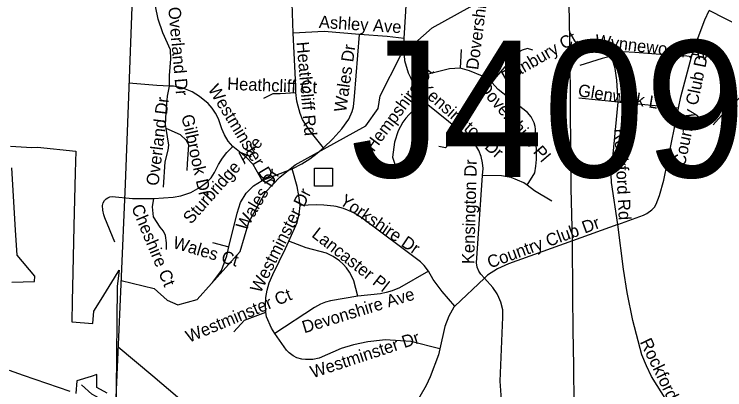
# Model space of a CAD drawing. Extents: x 1662474 to 1856135, y 779280 to 917889.
# Drawn here: x 1689866 to 1695335, y 806742 to 809631 of the extents above; entities that cross this region are included whole.
import ezdxf

# ---------------------------------------------------------------- set-up
doc = ezdxf.new("R2010")
doc.units = 0
for name, color, linetype in [('Exist Boundary Political City Limit New', 7, 'Continuous'), ('Exist Boundary Political CountyLine', 7, 'Continuous'), ('Exist Hydrographic Misc Water Feature', 7, 'Continuous'), ('Exist Road Non-System Structure Non-Sys Other Attributed CELL', 7, 'Continuous'), ('Exist Road Non-System Structure Non-Sys Other Number Label', 7, 'Continuous'), ('Exist Road Non-System Type 51', 7, 'Continuous'), ('Exist Road Non-System Type 51 Label', 7, 'Continuous'), ('Exist Road Primary NC UnDivided 4 Lane Attributed', 7, 'Continuous'), ('Exist Utilities Electrical Transmission Line', 7, 'Continuous'), ('Map Preparation Boundary City Limit Buffer Line', 7, 'Continuous')]:
    doc.layers.add(name, color=color, linetype=linetype)

msp = doc.modelspace()

# ---------------------------------------------------------------- linework, layer by layer
at = {"layer": 'Exist Boundary Political City Limit New'}
for points in [[(1689837.1, 808615.6), (1690000, 808604.7), (1690043.8, 808608.4), (1690340.6, 808577.1), (1690335.5, 808412.5), (1690325.8, 807999.6), (1690317.2, 807643.2), (1690312, 807424.1), (1690308.1, 807264.9), (1690471.4, 807251.4), (1690478.6, 807345.9), (1690534.4, 807436.7), (1690637, 807603.6), (1690672.9, 807662.2), (1690658.5, 807536.2), (1690650.1, 806742.6), (1690649.5, 806684.6)], [(1689847.1, 807570.9), (1690022, 807574.9), (1690023.4, 807615.5), (1689888.4, 807778.2), (1689876.1, 807969.6), (1689847.1, 808450.2)], [(1690297.2, 806728.5), (1689937.1, 806852.2), (1689828.1, 806890)], [(1690581.5, 806715.2), (1690502.5, 806759.9), (1690500.4, 806859.4), (1690457.6, 806845.6), (1690346.6, 806809.9), (1690339, 806714.1)]]:
    msp.add_lwpolyline(points, dxfattribs=at)
at = {"layer": 'Exist Boundary Political CountyLine'}
msp.add_lwpolyline([(1690220.4, 796849.4), (1690253.3, 797643.4), (1690261, 798032.2), (1690301.7, 799178.2), (1690347.6, 800042.9), (1690382.7, 800862.5), (1690417.8, 801672.6), (1690459.9, 802612.4), (1690490.6, 803379.9), (1690531.6, 804201.7), (1690578.3, 805157.6), (1690614.8, 805955.1), (1690649.3, 806683.1), (1690688.7, 807554.8), (1690723, 808322.5), (1690748.6, 808998.5), (1690777.2, 809760.4), (1690803.1, 810502.1), (1690838, 811298), (1690892.7, 812263.6), (1690949.1, 813375.2), (1690989.8, 814167.1), (1691300.1, 821093.4)], dxfattribs=at)
at = {"layer": 'Exist Hydrographic Misc Water Feature'}
msp.add_lwpolyline([(1690689.9, 807582.2), (1690942.8, 807521.7), (1691041.8, 807431.1), (1691124.8, 807396.6), (1691274.8, 807436.2), (1691603.8, 807807), (1691672.8, 808032), (1691800.9, 808262.6), (1691910.9, 808378.5), (1692027.9, 808471.3), (1692572.9, 808772), (1692665.9, 808904.7), (1692683.8, 809002.8), (1692837.8, 809311.5), (1693081.8, 809526.5), (1693374.9, 809688), (1693492.9, 809787.3)], dxfattribs=at)
at = {"layer": 'Exist Road Non-System Structure Non-Sys Other Attributed CELL'}
msp.add_lwpolyline([(1692177.5, 808447.2), (1692316.4, 808447.2), (1692316.4, 808308.1), (1692177.5, 808308.1)], close=True, dxfattribs=at)
at = {"layer": 'Exist Road Non-System Type 51'}
for p, q in [((1695584.6, 809469.9), (1695215.2, 809660.4)), ((1693305.4, 809359.4), (1693297.5, 809216.1)), ((1694513.8, 808954.4), (1694210.9, 808984.2)), ((1694978.2, 808908.2), (1694513.8, 808954.4)), ((1691773.1, 808351.8), (1692005.4, 808441.8)), ((1694511.1, 808012.9), (1694162.6, 807887.8)), ((1691391.1, 807874.4), (1691518, 807841.2)), ((1693485.1, 807600.4), (1693257.1, 807386.4))]:
    msp.add_line(p, q, dxfattribs=at)
for points in [[(1692014, 809484.9), (1692005.1, 809715.8), (1692005.4, 810474.9), (1692024, 810718.1), (1692023.2, 810769.6), (1692013.5, 810852.5), (1691986.8, 810965.9)], [(1691060, 809078), (1691061, 809160.4), (1691071.5, 809287.9), (1691067.4, 809357.5), (1691009.9, 809487.2), (1690972.6, 809593.8), (1690952.9, 809693.5), (1690940.6, 809800.6)], [(1692866.5, 809444.4), (1692885.6, 809740.2), (1692891.6, 809785.9)], [(1695079.1, 809303.7), (1695108.1, 809390.1), (1695182.2, 809587.2), (1695215.2, 809660.4)], [(1692522.6, 809474.9), (1692250.2, 809498.8), (1692014, 809484.9)], [(1692032.4, 809027.9), (1692034.2, 809076.7), (1692014, 809484.9)], [(1692245.8, 808604), (1692318, 808672.5), (1692387, 808749.9), (1692442.4, 808824.8), (1692467.9, 808881.4), (1692476, 808917.4), (1692485.1, 808998.8), (1692522.6, 809474.9)], [(1692866.5, 809444.4), (1692735.2, 809458.9), (1692522.6, 809474.9)], [(1695584.6, 809469.9), (1695551, 809398.4), (1695514.8, 809287.4), (1695497.1, 809195.9), (1695489, 809099.5), (1695482.5, 809057.8), (1695473.6, 809032.9), (1695449.1, 808987.2), (1695407.9, 808947.2), (1695330.8, 808873.9), (1695245.5, 808779.4)], [(1692921.6, 809135.8), (1692900.4, 809177.5), (1692873.4, 809271.7), (1692866.5, 809362.8), (1692866.5, 809444.4)], [(1693857.6, 809354.9), (1693816.1, 809365.9), (1693775.9, 809353.4), (1693729.8, 809329.4), (1693689.6, 809287.4), (1693641.6, 809226.9), (1693574.6, 809150.2), (1693541, 809105.6)], [(1695079.1, 809303.7), (1695042.1, 809309.2), (1694874.1, 809318.7), (1694641.9, 809336.5), (1694553.1, 809340.4), (1694464.4, 809307.7)], [(1694464.4, 809307.7), (1694390.1, 809291.1), (1694218.8, 809236.2)], [(1694513.8, 808954.4), (1694503.2, 809124.7), (1694490.4, 809213.4), (1694464.4, 809307.7)], [(1694978.2, 808908.2), (1694995.9, 808994.2), (1695079.1, 809303.7)], [(1693297.5, 809216.1), (1693217.1, 809209.5), (1692921.6, 809135.8)], [(1693541, 809105.6), (1693469.9, 809155.2), (1693371, 809196.6), (1693297.5, 809216.1)], [(1693028.4, 808955.4), (1692992.8, 808997.7), (1692958.1, 809052.2), (1692921.6, 809135.8)], [(1691060, 809078), (1690962.6, 809083.2), (1690747.1, 809099.5)], [(1691035.4, 808752.2), (1691029.9, 808782.8), (1691034.2, 808878.2), (1691045.2, 809000.4), (1691060, 809078)], [(1691547.6, 808614.2), (1691512.8, 808654.4), (1691483.1, 808703.2), (1691462.9, 808748.4), (1691436.9, 808827.4), (1691415.9, 808869.4), (1691389.4, 808908.2), (1691357.6, 808943.1), (1691291.2, 808998.5), (1691235.6, 809032.9), (1691157.4, 809064.4), (1691092.5, 809077.5), (1691060, 809078)], [(1693812.9, 808314.8), (1693873.6, 808410), (1693881.4, 808462), (1693885.9, 808514.2), (1693885.9, 808580.1), (1693878.6, 808745.8), (1693875.4, 808767.5), (1693867.5, 808795.9), (1693844.1, 808841.5), (1693816.1, 808875.4), (1693591.9, 809052.8), (1693541, 809105.6)], [(1691786.5, 808986.4), (1691860, 809021.6), (1691913.2, 809021.6), (1692032.4, 809027.9)], [(1692245.8, 808604), (1692144.5, 808732.6), (1692102.5, 808792.7), (1692085.9, 808821.6), (1692066.8, 808866.7), (1692050.2, 808923.9), (1692041.9, 808962), (1692032.4, 809027.9)], [(1693028.4, 808955.4), (1692959.9, 808910), (1692904.9, 808860.4), (1692879.6, 808831.5), (1692857.9, 808800.4), (1692822.1, 808734.4), (1692793.9, 808646.8), (1692777, 808530.8), (1692803.2, 808454.9)], [(1693301.1, 808731.2), (1693036.6, 808944.9), (1693028.4, 808955.4)], [(1694511.1, 808012.9), (1694462.5, 808337.4), (1694460.6, 808395.6), (1694513.8, 808954.4)], [(1694511.1, 808012.9), (1694710.1, 808085.9), (1694735.2, 808097.9), (1694774.4, 808127.4), (1694793.2, 808147.9), (1694807.9, 808169.6), (1694831.9, 808236.9), (1694865.4, 808355.4), (1694978.2, 808908.2)], [(1691013.8, 808299.5), (1691026.6, 808494.9), (1691050.9, 808584.4), (1691055.5, 808624.4), (1691035.4, 808752.2)], [(1691198, 808427.6), (1691199.4, 808480.4), (1691210.6, 808625.8), (1691189.9, 808662.8), (1691146.6, 808702.7), (1691035.4, 808752.2)], [(1693301.1, 808731.2), (1693185.9, 808601.9), (1693135, 808612.7)], [(1693470.6, 808389.9), (1693474.1, 808444.4), (1693470.4, 808488.5), (1693459.4, 808536.8), (1693441, 808582.5), (1693418.8, 808620.5), (1693387.8, 808659.1), (1693359.4, 808685.4), (1693301.1, 808731.2)], [(1690939.8, 808214), (1691089.9, 808223.7), (1691148.1, 808232.9), (1691225.1, 808260.7), (1691296.5, 808300.4), (1691348.1, 808338.7), (1691381.5, 808372.8), (1691408.2, 808412.7), (1691439, 808475.9), (1691468.1, 808523.4), (1691502.2, 808567.8), (1691547.6, 808614.2)], [(1691773.1, 808351.8), (1691704.1, 808474.4), (1691651.9, 808532.4), (1691547.6, 808614.2)], [(1692005.4, 808441.8), (1692079.9, 808480.6), (1692140.5, 808518.4), (1692197.5, 808561.8), (1692245.8, 808604)], [(1692067.6, 808160.7), (1692057.1, 808233.4), (1692042.9, 808305.6), (1692005.4, 808441.8)], [(1691518, 807841.2), (1691582.6, 808100.4), (1691607.5, 808181.9), (1691650.2, 808253.6), (1691706.6, 808311.6), (1691773.1, 808351.8)], [(1693485.1, 807600.4), (1693457.4, 807631.6), (1693442.6, 807654.9), (1693430, 807685.9), (1693424.2, 807718.7), (1693470.6, 808389.9)], [(1693812.9, 808314.8), (1693789.4, 808332.9), (1693690.6, 808374.1), (1693616.4, 808388.8), (1693470.6, 808389.9)], [(1694005.1, 808192.4), (1693871.5, 808271.2), (1693812.9, 808314.8)], [(1690639.8, 807878.5), (1690563.4, 808064.9), (1690556.4, 808086.7), (1690548.6, 808123.2), (1690545, 808160.4), (1690549.5, 808179.9), (1690561, 808198.8), (1690572.9, 808210.6), (1690586.8, 808219.5), (1690602.2, 808225.5), (1690618.5, 808227.9), (1690777.4, 808214), (1690939.8, 808214)], [(1691039, 807821.6), (1691039, 807871.2), (1691029, 807928.9), (1691013.8, 807961.8), (1690988.6, 807994.2), (1690938.5, 808072.5), (1690931.1, 808150.2), (1690939.8, 808214)], [(1691978.4, 807885.1), (1692043.6, 808028.9), (1692060, 808092.4), (1692067.6, 808160.7)], [(1693053.6, 807653.6), (1693021.4, 807697.4), (1692993, 807726.9), (1692543.9, 808062.8), (1692474.1, 808105), (1692399.1, 808136.9), (1692345, 808152.9), (1692325.9, 808155.4), (1692247.9, 808163.4), (1692189.6, 808165.7), (1692067.6, 808160.7)], [(1694888, 806657), (1694772, 806843.9), (1694731.4, 806925.9), (1694697.1, 807010.4), (1694627.6, 807273.9), (1694582.8, 807491.2), (1694554.6, 807670.9), (1694511.1, 808012.9)], [(1691802.5, 807339.4), (1691799.9, 807393.5), (1691803, 807451.5), (1691812.8, 807508.5), (1691827.6, 807564.7), (1691855.2, 807629.8), (1691953.9, 807829.4), (1691978.4, 807885.1)], [(1692510.1, 807461.2), (1692480.9, 807579.9), (1692465.1, 807614.8), (1692445.5, 807648.1), (1692423.2, 807679.9), (1692397.2, 807708.5), (1692368.6, 807734.4), (1692320.9, 807767), (1692268.6, 807791.9), (1692112.8, 807833.4), (1691978.4, 807885.1)], [(1694162.6, 807887.8), (1693669.1, 807710.4), (1693586.1, 807672.8), (1693509, 807622.7), (1693485.1, 807600.4)], [(1691358.6, 807531.9), (1691392, 807567.8), (1691460.2, 807660.9), (1691501.4, 807773), (1691518, 807841.2)], [(1693053.6, 807653.6), (1692832.6, 807526.9), (1692774.1, 807502.7), (1692729.5, 807489.4), (1692683.9, 807480.1), (1692510.1, 807461.2)], [(1693257.1, 807386.4), (1693161, 807496.9), (1693091.1, 807590.4), (1693053.6, 807653.6)], [(1693574.4, 806522.2), (1693609.5, 806629.8), (1693615.1, 806699.6), (1693606.6, 806808.2), (1693627.4, 807301.7), (1693626.1, 807356), (1693611.1, 807417.2), (1693596.9, 807452.6), (1693582.5, 807480.9), (1693550.5, 807527.9), (1693485.1, 807600.4)], [(1692510.1, 807461.2), (1692300.4, 807425.5), (1692261.9, 807415), (1692224, 807400.4), (1692176.8, 807375.2), (1691872.9, 807175.4)], [(1693257.1, 807386.4), (1693248.9, 807378.2), (1693209.9, 807307.4), (1693179.9, 807230), (1693142.6, 807056.5)], [(1691556.6, 807187.5), (1691637.6, 807277.2), (1691802.5, 807339.4)], [(1691872.9, 807175.4), (1691845.5, 807216.1), (1691807.2, 807302.2), (1691802.5, 807339.4)], [(1693142.6, 807056.5), (1692919, 807113.5), (1692721.6, 807126.6), (1692699.4, 807125), (1692587, 807111.1), (1692476.2, 807088), (1692381.5, 807059.4), (1692212.1, 806985.7), (1692165.2, 806975.4), (1692107.8, 806973.9), (1692078.6, 806977.8), (1692041.9, 806987.2), (1692013.2, 807003.8), (1691982.5, 807026.9), (1691961.5, 807046.9), (1691872.9, 807175.4)], [(1693142.6, 807056.5), (1693131.1, 807011.9), (1693068.4, 806842.9), (1693037.6, 806775.2), (1692988, 806690.7), (1692972, 806668.9), (1692937.4, 806636.6), (1692895.6, 806614), (1692737.6, 806565.7), (1692705.1, 806559.2)], [(1691020.9, 806629.5), (1690641.9, 806652.4), (1690519.6, 806677.5), (1690463.6, 806708.2), (1690383.6, 806780.4)]]:
    msp.add_lwpolyline(points, dxfattribs=at)
at = {"layer": 'Exist Road Primary NC UnDivided 4 Lane Attributed'}
msp.add_lwpolyline([(1694176.4, 806631.6), (1694173.5, 806923.1), (1694168.8, 807203.4), (1694165.8, 807463.9), (1694162.4, 807889.3), (1694153.9, 808289.8), (1694151.3, 808546.3), (1694148.1, 808957.2), (1694145, 809299.7), (1694137.5, 809708.4), (1694127.1, 810126.2), (1694127.1, 810598.1), (1694121.9, 810894.7), (1694124.5, 811150.3), (1694133, 811288.3)], dxfattribs=at)
at = {"layer": 'Exist Utilities Electrical Transmission Line'}
msp.add_lwpolyline([(1690667, 807073.7), (1690933.6, 806848.3), (1691312.5, 806526.5), (1691736.7, 806164.4), (1692143.2, 805812.4), (1692470, 805535), (1692830.7, 805223.1), (1693263.3, 804850.9), (1693594.2, 804579.3), (1693733.4, 804448.4), (1694040.2, 804189.1), (1694380.9, 803897.6), (1694775.8, 803555.4), (1695108.4, 803273.9), (1695295.6, 803112.9), (1695566.6, 802881.6), (1695706.3, 802764.8), (1695999.3, 802513.4), (1696154.8, 802380.9), (1696469.3, 802109.3), (1696720.3, 801895.7), (1697055.3, 801612.2), (1697308.3, 801399), (1697413.9, 801312.5)], dxfattribs=at)
at = {"layer": 'Map Preparation Boundary City Limit Buffer Line'}
for points in [[(1689837.1, 808615.6), (1690000, 808604.7), (1690043.8, 808608.4), (1690340.6, 808577.1), (1690335.5, 808412.5), (1690325.8, 807999.6), (1690317.2, 807643.2), (1690312, 807424.1), (1690308.1, 807264.9), (1690471.4, 807251.4), (1690478.6, 807345.9), (1690534.4, 807436.7), (1690637, 807603.6), (1690672.9, 807662.2), (1690658.5, 807536.2), (1690650.1, 806742.6), (1690649.5, 806684.6)], [(1689847.1, 807570.9), (1690022, 807574.9), (1690023.4, 807615.5), (1689888.4, 807778.2), (1689876.1, 807969.6), (1689847.1, 808450.2)], [(1690297.2, 806728.5), (1689937.1, 806852.2), (1689828.1, 806890)], [(1690581.5, 806715.2), (1690502.5, 806759.9), (1690500.4, 806859.4), (1690457.6, 806845.6), (1690346.6, 806809.9), (1690339, 806714.1)]]:
    msp.add_lwpolyline(points, dxfattribs=at)

# ---------------------------------------------------------------- texts
at = {"layer": 'Exist Road Non-System Structure Non-Sys Other Number Label'}
msp.add_text('J409', height=1049.86, dxfattribs=at).set_placement((1692455.3, 808377.6))
at = {"layer": 'Exist Road Non-System Type 51 Label'}
for s, rotation, p in [('Dovershire Ct', 82.6827, (1693436.6, 809199.3)), ('Overland Dr', 275.0918, (1691051.3, 809682.8)), ('Ashley Ave', 356.2833, (1692209, 809526.3)), ('Danbury Ct', 30.013, (1693650.5, 809097.7)), ('Wynnewood Ave', 353.015, (1694333.3, 809382.9)), ('Heathcliff Rd', 274.9243, (1692038.7, 809415.9)), ('Wales Dr', 81.9159, (1692419.8, 808873.8)), ('Country Club Dr', 78.2476, (1695027.4, 808454.2)), ('Hempshire Ct', 53.2078, (1692633.2, 808566.6)), ('Heathcliff Ct', 357.7568, (1691503.7, 809050)), ('Dovershire Pl', 310.4867, (1693433.4, 809064.2)), ('Westminster Dr', 301.1706, (1691353.5, 809055.5)), ('Kensington Dr', 318.798, (1692974.9, 809044.7)), ('Glenwick Ln', 350.9047, (1694200.8, 809001.4)), ('Overland Dr', 83.1339, (1690975.4, 808307.9)), ('Gilbrook Dr', 282.6456, (1691151.4, 808848.7)), ('Rockford Rd', 272.9015, (1694484, 808750.1)), ('Sturbridge Ave', 48.4263, (1691226.4, 808010.3)), ('Kensington Dr', 88.5296, (1693406.4, 807708.1)), ('Wales Dr', 59.4544, (1691648.5, 807959)), ('Westminster Dr', 63.2336, (1691761, 807479.3)), ('Yorkshire Dr', 325.8562, (1692363.1, 808174.7)), ('Cheshire Ct', 292.6083, (1690764.9, 808145.8)), ('Country Club Dr', 20.2243, (1693527.8, 807674.4)), ('Lancaster Pl', 322.0143, (1692148.8, 807924.1)), ('Wales Ct', 343.569, (1691080.3, 807834.6)), ('Westminster Ct', 22.7054, (1691210.6, 807102.9)), ('Devonshire Ave', 17.0329, (1692098.4, 807176.1)), ('Westminster Dr', 18.2173, (1692163.5, 806830.4)), ('Rockford Rd', 295.5887, (1694679.9, 807110.7))]:
    msp.add_text(s, height=95, rotation=rotation, dxfattribs=at).set_placement(p)

doc.saveas('drawing.dxf')
